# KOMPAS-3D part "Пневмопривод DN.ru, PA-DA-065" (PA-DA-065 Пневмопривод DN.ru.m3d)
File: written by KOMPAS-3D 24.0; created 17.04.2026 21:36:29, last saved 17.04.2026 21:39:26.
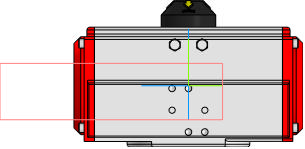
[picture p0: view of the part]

Document properties: Автор: DN.ru; Полное имя файла: C:\Работа\PA-DA-х Пневмопривод DN.ru\065\PA-DA-065 Пневмопривод DN.ru.m3d

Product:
- Part/product: Пневмопривод DN.ru  | designation PA-DA-065
    Масса: 2
    Раздел спецификации: Прочие изделия
    Примечание: D290-00294

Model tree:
1. Операция без истории:1

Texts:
  PA-DA-065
